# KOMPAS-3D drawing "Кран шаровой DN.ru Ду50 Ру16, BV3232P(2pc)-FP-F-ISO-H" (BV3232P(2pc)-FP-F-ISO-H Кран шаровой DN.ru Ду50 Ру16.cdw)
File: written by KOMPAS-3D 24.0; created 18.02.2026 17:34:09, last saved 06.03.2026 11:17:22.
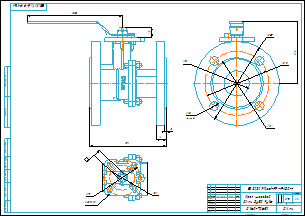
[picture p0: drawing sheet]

Document properties: Автор: R2D2; Форматы листов документа: A2; Полное имя файла: BV3232P(2pc)-FP-F-ISO-H Кран шаровой DN.ru Ду50 Ру16.m3d; Масса: 8.78; Наименование: Кран шаровой DN.ru Ду50 Ру16; Количество листов документа: 1; Примечание: D160-70652

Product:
- Part/product: Кран шаровой DN.ru Ду50 Ру16  | designation BV3232P(2pc)-FP-F-ISO-H
    Масса: 8.78
    Раздел спецификации: Прочие изделия
    Форматы листов документа: A2
    Примечание: D160-70652

Views: Проекционный вид 2, Проекционный вид 3
Referenced files in E:\Работа\Зайцев\BV3232P(2pc)-FP-F-ISO-H Кран шаровой DN.ru Ду15-300 Ру16-40\DN50 PN40\исходные материалы\: BV3232P(2pc)-FP-F-ISO-H Кран шаровой DN.ru Ду50 Ру40.m3d
Referenced files in E:\Работа\Зайцев\Для компаса\: чертеж DN.ru А3.cdt
Referenced files in E:\Работа\Зайцев\BV3232P(2pc)-FP-F-ISO-H Кран шаровой DN.ru Ду15-300 Ру16-40\DN50 PN16\: BV3232P(2pc)-FP-F-ISO-H Кран шаровой DN.ru Ду50 Ру16.m3d
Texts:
  BV3232P(2pc)-FP-F-ISO-H
  ISO 5211
  чертеж DN.ru А3.cdt
  Кран шаровой
  DN.ru Ду50 Ру16
  Кран шаровой DN.ru Ду50 Ру16
  BV3232P(2pc)-FP-F-ISO-H Кран шаровой DN.ru Ду50 Ру16
Dimensions and other numbers on the sheet: 0; 3; 4; 120; 165; 125; 102; 50; 18; 4 отв.; 70; 14; 1:1; 1; 2; 8,78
